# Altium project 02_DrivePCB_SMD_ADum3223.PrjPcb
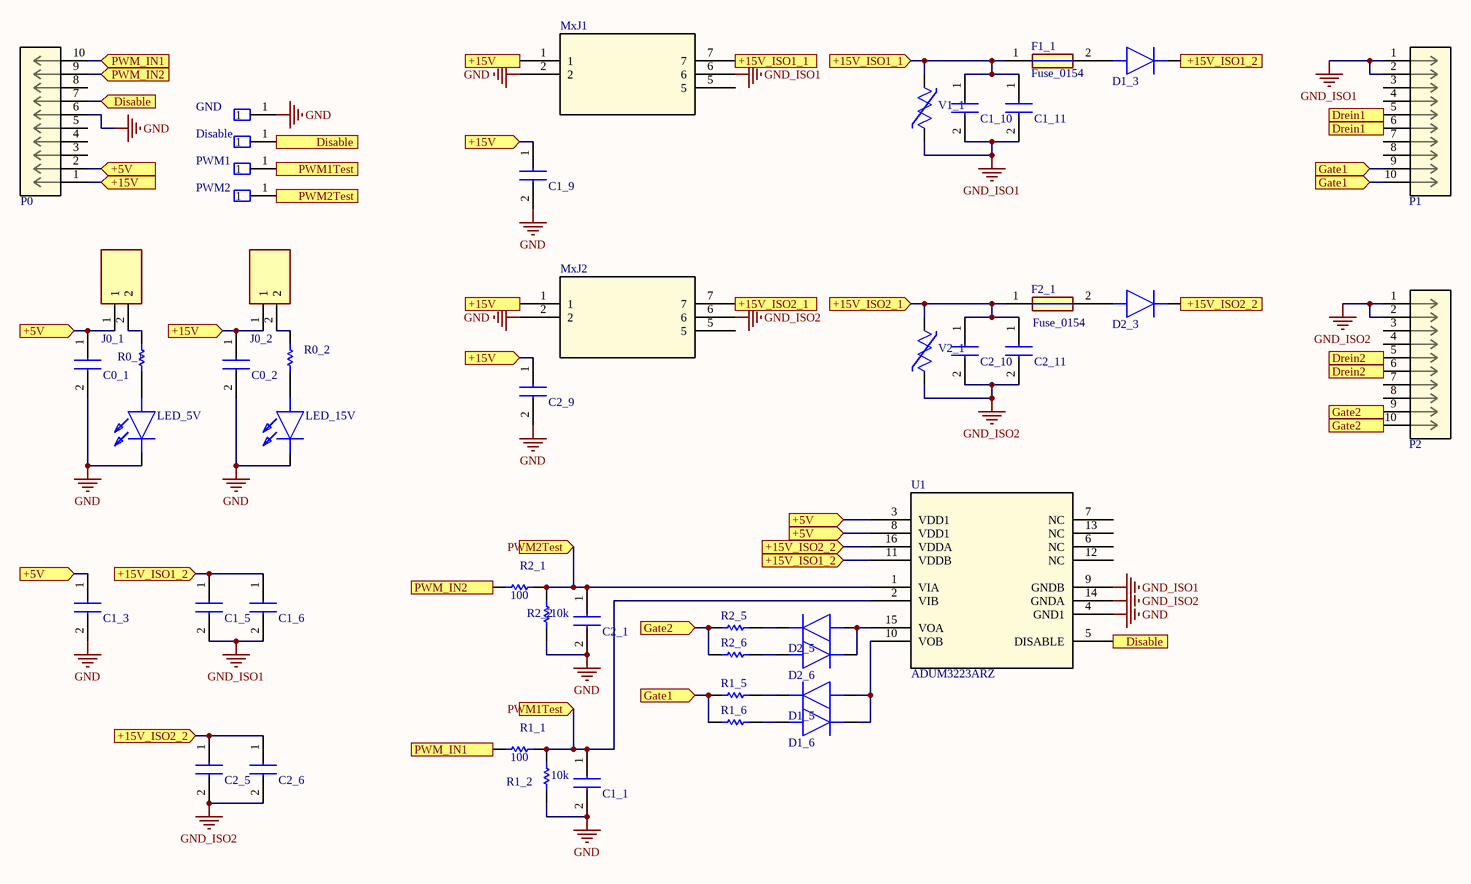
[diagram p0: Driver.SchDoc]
1 sheet, 49 parts. Net scope: flat (ports and power ports of the same name join across sheets).
Board file: Driver.PcbDoc

## Sheet Driver.SchDoc
size A3

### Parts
C0_1  CAP  [CAP1206_SMD]  (value not drawn)
C0_2  CAP  [CAP1206_SMD]  (value not drawn)
C1_1  CAP  [CAP1206_SMD]  (value not drawn)
C1_3  CAP  [CAP1206_SMD]  (value not drawn)
C1_5  CAP  [CAP1206_SMD]  (value not drawn)
C1_6  CAP  [CAP_ELETRO_SMD_6.3x7.7]  (value not drawn)
C1_9  CAP  [CAP1206_SMD]  (value not drawn)
C1_10  CAP  [CAP1206_SMD]  (value not drawn)
C1_11  CAP  [CAP_ELETRO_SMD_6.3x7.7]  (value not drawn)
C2_1  CAP  [CAP1206_SMD]  (value not drawn)
C2_5  CAP  [CAP1206_SMD]  (value not drawn)
C2_6  CAP  [CAP_ELETRO_SMD_6.3x7.7]  (value not drawn)
C2_9  CAP  [CAP1206_SMD]  (value not drawn)
C2_10  CAP  [CAP1206_SMD]  (value not drawn)
C2_11  CAP  [CAP_ELETRO_SMD_6.3x7.7]  (value not drawn)
D1_3  TLHR5400-AS12Z  [Diode_SMD_SOD123]  (value not drawn)
D1_5  TLHR5400-AS12Z  [Diode_SMD_SOD123]  (value not drawn)
D1_6  TLHR5400-AS12Z  [Diode_SMD_SOD123]  (value not drawn)
D2_3  TLHR5400-AS12Z  [Diode_SMD_SOD123]  (value not drawn)
D2_5  TLHR5400-AS12Z  [Diode_SMD_SOD123]  (value not drawn)
D2_6  TLHR5400-AS12Z  [Diode_SMD_SOD123]  (value not drawn)
Disable  TB004-508-02BE  [TestPoint]  (value not drawn)
F1_1  Fuse_0154  [Fuse_0154]
F2_1  Fuse_0154  [Fuse_0154]
GND  TB004-508-02BE  [TestPoint]  (value not drawn)
J0_1  TB004-508-02BE  [HEADER_MALE_TH_2P_2.54]  (value not drawn)
J0_2  TB004-508-02BE  [HEADER_MALE_TH_2P_2.54]  (value not drawn)
LED_5V  TLHR5400-AS12Z  [LED_TH_2.54 (small)]  (value not drawn)
LED_15V  TLHR5400-AS12Z  [LED_TH_2.54 (small)]  (value not drawn)
MxJ1  MGJ2D152005SC  [MGJ2_MUR]  (value not drawn)
MxJ2  MGJ2D152005SC  [MGJ2_MUR]  (value not drawn)
P0  5103311-1  [CONN_5103311-1_TYC]  (value not drawn)
P1  5103311-1  [CONN_5103311-1_TYC]  (value not drawn)
P2  5103311-1  [CONN_5103311-1_TYC]  (value not drawn)
PWM1  TB004-508-02BE  [TestPoint]  (value not drawn)
PWM2  TB004-508-02BE  [TestPoint]  (value not drawn)
R0_1  (no value)  [Resis_SMD_1206]
R0_2  (no value)  [Resis_SMD_1206]
R1_1  Name: 100  [Resis_SMD_1206]
R1_2  Name: 10k  [Resis_SMD_1206]
R1_5  Res1  [Resis_SMD_1206]  (value not drawn)
R1_6  Res1  [Resis_SMD_1206]  (value not drawn)
R2_1  Name: 100  [Resis_SMD_1206]
R2_2  Name: 10k  [Resis_SMD_1206]
R2_5  Res1  [Resis_SMD_1206]  (value not drawn)
R2_6  Res1  [Resis_SMD_1206]  (value not drawn)
U1  ADUM3223ARZ  [ADum3223]
V1_1  B72220S131K101  [CAP_TH _5.08]  (value not drawn)
V2_1  B72220S131K101  [CAP_TH _5.08]  (value not drawn)

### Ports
+5V (in), +15V (in), +15V_ISO1_1 (in), +15V_ISO1_2 (in), +15V_ISO2_1 (in), +15V_ISO2_2 (in), Disable (in), Drein1 (in), Drein2 (in), Gate1 (in), Gate2 (in), PWM1Test (in), PWM2Test (in), PWM_IN1 (in), PWM_IN2 (in)

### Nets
GND: C0_1.2 C0_2.2 C1_1.2 C1_3.2 C1_9.2 C2_1.2 C2_9.2 GND.1 LED_5V.1(K) LED_15V.1(K) MxJ1.2 MxJ2.2 P0.6 R1_2.1 R2_2.1 U1.4(GND1)
GND_ISO1: C1_5.2 C1_6.2 C1_10.2 C1_11.2 MxJ1.6 P1.1 P1.2 U1.9(GNDB) V1_1.2
GND_ISO2: C2_5.2 C2_6.2 C2_10.2 C2_11.2 MxJ2.6 P2.1 P2.2 U1.14(GNDA) V2_1.2
NetC0_1_1: C0_1.1 C1_3.1 J0_1.1 P0.2 U1.3(VDD1) U1.8(VDD1) ; port +5V
NetC0_2_1: C0_2.1 C1_9.1 C2_9.1 J0_2.1 MxJ1.1 MxJ2.1 P0.1 ; port +15V
NetC1_1_1: C1_1.1 PWM1.1 R1_1.2 R1_2.2 U1.2(VIB) ; port PWM1Test
NetC1_5_1: C1_5.1 C1_6.1 D1_3.1(K) U1.11(VDDB) ; port +15V_ISO1_2
NetC1_10_1: C1_10.1 C1_11.1 F1_1.1 MxJ1.7 V1_1.1 ; port +15V_ISO1_1
NetC2_1_1: C2_1.1 PWM2.1 R2_1.2 R2_2.2 U1.1(VIA) ; port PWM2Test
NetC2_5_1: C2_5.1 C2_6.1 D2_3.1(K) U1.16(VDDA) ; port +15V_ISO2_2
NetC2_10_1: C2_10.1 C2_11.1 F2_1.1 MxJ2.7 V2_1.1 ; port +15V_ISO2_1
NetD1_3_2: D1_3.2(A) F1_1.2
NetD1_5_1: D1_5.1(K) R1_5.1
NetD1_5_2: D1_5.2(A) D1_6.1(K) U1.10(VOB)
NetD1_6_2: D1_6.2(A) R1_6.1
NetD2_3_2: D2_3.2(A) F2_1.2
NetD2_5_1: D2_5.1(K) R2_5.1
NetD2_5_2: D2_5.2(A) D2_6.1(K) U1.15(VOA)
NetD2_6_2: D2_6.2(A) R2_6.1
NetDisable_1: Disable.1 P0.7 U1.5(DISABLE) ; port Disable
NetJ0_1_2: J0_1.2 R0_1.2
NetJ0_2_2: J0_2.2 R0_2.2
NetLED_5V_2: LED_5V.2(A) R0_1.1
NetLED_15V_2: LED_15V.2(A) R0_2.1
NetP0_9: P0.9 R2_1.1 ; port PWM_IN2
NetP0_10: P0.10 R1_1.1 ; port PWM_IN1
NetP1_5: P1.5 P1.6 ; port Drein1
NetP1_9: P1.9 P1.10 R1_5.2 R1_6.2 ; port Gate1
NetP2_5: P2.5 P2.6 ; port Drein2
NetP2_9: P2.9 P2.10 R2_5.2 R2_6.2 ; port Gate2

Not connected (* = marked no-connect by the designer): MxJ1 5; MxJ2 5; P0 3 4 5 8; P1 3 4 7 8; P2 3 4 7 8; U1 6(NC) 7(NC) 12(NC) 13(NC)

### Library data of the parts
C0_1 C0_2 C1_1 C1_3 C1_5 C1_6 C1_9-C1_11 C2_1 C2_5 C2_6 C2_9-C2_11 = CAP: Capacitor; Manufacturer_Name: Kemet; Manufacturer_Part_Number: C1206X475K3RACAUTO7210
D1_3 D1_5 D1_6 D2_3 D2_5 D2_6 = Diode: Manufacturer_Name: Vishay
Disable GND PWM1 PWM2 = TestPoint: Connector; Manufacturer_Name: CUI Devices
F1_1 F2_1 = Fuse_0154: Fuse; Manufacturer_Name: LITTELFUSE; Manufacturer_Part_Number: 0154002.DRL
J0_1 J0_2 = Con_Header_2P: Connector; Manufacturer_Name: CUI Devices
LED_5V LED_15V = LED: Manufacturer_Name: Vishay
MxJ1 MxJ2 = MGJ2D152005SC: No Description Available; Mfr_Name: Murata
P0-P2 = Con_Header_5103311-1: No Description Available; Mfr_Name: TE Connectivity
R0_1 R0_2 = Resistor: Name: 2.7k
R1_1 R1_2 R1_5 R1_6 R2_1 R2_2 R2_5 R2_6 = Resistor
U1 = ADUM3223ARZ: No Description Available; Vendor: Analog Devices Inc; Built_By: EMA_UL_Team; SourceLibrary: Analog_2015-12-15
V1_1 V2_1 = Varistor: No Description Available; Mfr_Name: TDK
